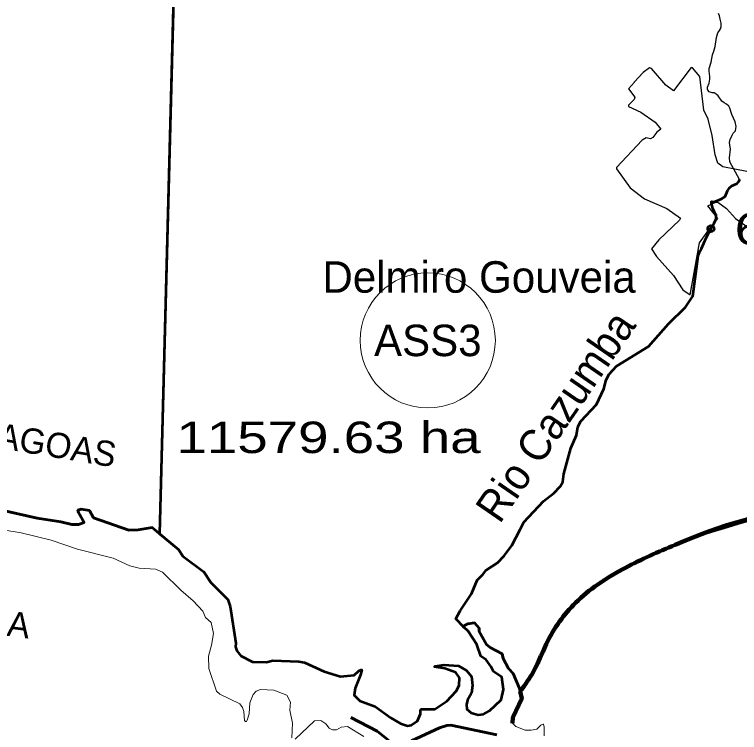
# Model space of a CAD drawing. Extents: x -1643653 to 4543381, y 1624270 to 13878484.
# Drawn here: x 598915 to 610437, y 8953418 to 8964825 of the extents above; entities that cross this region are included whole.
import ezdxf
from ezdxf.enums import TextEntityAlignment as Align

# ---------------------------------------------------------------- set-up
doc = ezdxf.new("R2010")
doc.units = 0
doc.header["$LTSCALE"] = 200
doc.header["$PDMODE"] = 32
doc.header["$PDSIZE"] = 100
doc.linetypes.add('LONG_DASH_SHORT_DASH', pattern=[9.9, 6, -1.2, 1.5, -1.2])
for name, color, linetype, lineweight in [('1', 7, 'Continuous', 13), ('21', 7, 'Continuous', 25), ('24', 7, 'Continuous', 25), ('25', 7, 'Continuous', 13), ('26', 7, 'Continuous', 106), ('27', 7, 'Continuous', 53), ('28', 7, 'Continuous', 53), ('45', 7, 'Continuous', 13), ('7', 7, 'LONG_DASH_SHORT_DASH', 60)]:
    doc.layers.add(name, color=color, linetype=linetype, lineweight=lineweight)
for name, color, linetype in [('41', 7, 'Continuous'), ('42', 7, 'Continuous'), ('49', 7, 'Continuous'), ('63', 7, 'Continuous')]:
    doc.layers.add(name, color=color, linetype=linetype)

msp = doc.modelspace()

# ---------------------------------------------------------------- linework, layer by layer
at = {"layer": '1', "lineweight": 25}
msp.add_spline([(814781, 9009175.5), (814787.2, 9009173.4), (814796.9, 9009173.4), (814799.4, 9009172.4), (814805.1, 9009174.5), (814805.6, 9009176.5), (814811.7, 9009179.5), (814811.7, 9009179.5), (814801.5, 9009181), (814790.7, 9009181.5), (814784.1, 9009183.1), (814777.4, 9009185.1), (814778.4, 9009175.5)], degree=3, dxfattribs=at)
at = {"layer": '21'}
for points in [[(609804.3, 8963841.6), (609692.8, 8963976.2), (609666.6, 8963982.7), (609387.8, 8963613.5), (609268.7, 8963704.3), (609037.7, 8963969.7), (609005.2, 8963976.3), (608907.9, 8963902.9), (608765.2, 8963749.4), (608768.4, 8963752.9)], [(608768.4, 8963752.9), (608671.8, 8963644.5), (608771.6, 8963513.5), (608763, 8963472.8), (608674.7, 8963384.3), (608674.6, 8963362.6), (608871.1, 8963271.6), (609098.6, 8963116.9), (609185.2, 8963006.2), (609122.6, 8962955.4), (609059.5, 8962870.7), (609020.3, 8962848.1), (608953.3, 8962867.3), (608890.2, 8962830.9), (608482.3, 8962396.3), (608482.2, 8962374.6), (608698.7, 8962069.7), (608927.4, 8961894.7), (609281.9, 8961745.5), (609500, 8961592.1), (609485, 8961557.5), (609154.4, 8961246.1), (609040.8, 8961101.4), (609119, 8960979.5), (609387.8, 8960677.5), (609534.3, 8960449.1), (609653.8, 8960372.8), (609800.8, 8961196.1)], [(610640.9, 8962315.2), (610391, 8962365.2), (610171.2, 8962405.2), (610091.2, 8962465.2), (610051.2, 8962595.2), (610001.3, 8962905.1), (609941.3, 8963165), (609871.4, 8963304.9), (609804.3, 8963841.6)], [(609800.8, 8961196.1), (609951.3, 8961405.5), (610091.2, 8961585.5), (609931.3, 8961785.4), (610001.3, 8961815.4), (610061.2, 8961845.4), (610091.2, 8961845.4), (610231.1, 8961745.4), (610371.1, 8961585.5), (610570.9, 8961445.5)]]:
    msp.add_lwpolyline(points, dxfattribs=at)
at = {"layer": '24'}
for points in [[(610371.4, 8962976.2), (610379.8, 8963013.8), (610382.1, 8963047.9), (610367.5, 8963120), (610314.8, 8963239.1), (610282.3, 8963338.2), (610265.4, 8963370.2), (610232.8, 8963402.2), (610193.3, 8963421.2), (610157.8, 8963448.2), (610095.6, 8963532.2), (610066.7, 8963561.2), (610036.6, 8963580.2), (610003.6, 8963581.1), (609956.2, 8963599.1), (609936, 8963623.1), (609928.6, 8963640.1), (609929.5, 8963669.1), (609954.4, 8963735.3), (609968.3, 8963800.4), (609967.7, 8963842.5), (609955.3, 8963923.6), (609957.6, 8963969.7), (609987.3, 8964065.8), (610009.7, 8964184.1), (610029.9, 8964242.2), (610049.4, 8964318.3), (610070.6, 8964459.6), (610090.6, 8964534.7), (610118.8, 8964569.8), (610136.5, 8964599.9), (610143.2, 8964627), (610143.3, 8964686.1), (610132.5, 8964751.1), (610117.5, 8964805.2), (610101.9, 8964839.2)], [(609982.1, 8961422.7), (610037.1, 8961507.9), (610064.5, 8961578.1), (610064.2, 8961638.2), (610040.6, 8961677.2), (610038.1, 8961690.2), (610013.3, 8961743.3), (609992.6, 8961823.3), (609993.5, 8961853.4), (609997.6, 8961856.4), (610025.7, 8961851.5), (610048.1, 8961855.5), (610148.5, 8961896.7), (610207.6, 8961933.9), (610245.1, 8962026.1), (610277.6, 8962073.2), (610312.8, 8962103.3), (610398.6, 8962138.5), (610419.5, 8962164.6), (610435.7, 8962195.6), (610437.2, 8962206.7), (610284.5, 8962485.8), (610279.8, 8962547.9), (610295.5, 8962684.2), (610281.3, 8962752.3), (610279.8, 8962791.3), (610289, 8962838.4), (610320, 8962910.6), (610338.8, 8962938.6), (610371.4, 8962976.2)], [(606950.7, 8956641.4), (607010.7, 8956757.8), (607320.7, 8957095.6), (607486.4, 8957220.9), (607586.3, 8957325.3), (607630.8, 8957401.7), (607645.7, 8957526.8), (607756.7, 8957933.8), (607847.4, 8958140.8), (607868.9, 8958272.7), (607915.5, 8958363.8), (608166.1, 8958629.3), (608279.8, 8958879.3), (608317, 8959022.3), (608365.8, 8959111.5), (608484.8, 8959236.8), (608990.2, 8959553.2), (609306.9, 8959910.2), (609576.6, 8960175.8), (609697.7, 8960350), (609780.5, 8960992), (609809.8, 8961070.9), (609834, 8961110), (609904.8, 8961278.4), (609982.1, 8961422.7)], [(606039.3, 8955103.8), (605929.6, 8955224.5), (605999.4, 8955353.7), (606180, 8955619.3), (606269.2, 8955840.2), (606360.2, 8955926.9), (606411.5, 8955999.5), (606589.9, 8956112.1), (606699.8, 8956226.1), (606821.6, 8956390.6), (606950.7, 8956641.4)]]:
    msp.add_lwpolyline(points, dxfattribs=at)
msp.add_point((609982.1, 8961422.7), dxfattribs=at)
at = {"layer": '25'}
for points in [[(604895.8, 8953649.4), (604648, 8953830.8), (604402.7, 8953921.2), (604313.5, 8954010.1), (604331.8, 8954124.8), (604416, 8954332.4), (604432.7, 8954411.5), (604424.9, 8954413.6), (604386.7, 8954398.7), (604315.2, 8954330), (604098.3, 8954307.6), (603837.5, 8954388.2), (603522.6, 8954529.5), (603434.3, 8954545.5), (603019.3, 8954562.1), (602920.8, 8954535.9), (602695.5, 8954541), (602512.3, 8954636.9), (602447.2, 8954715.8), (602427.7, 8954781.3), (602434.1, 8954838.6), (602343.7, 8955420.5), (602307.6, 8955528.7), (602034.6, 8955801.4), (601924, 8955971.4), (601588.5, 8956218.1), (601523.3, 8956327.4), (601101.6, 8956673.9), (600881.9, 8956635.9), (600732.9, 8956633.6), (600171.5, 8956830.7), (600105.7, 8956947.1), (599975.9, 8956965.8), (599923.2, 8956948.3), (599930.5, 8956912), (600022.6, 8956753.4), (599933.1, 8956722.5), (599825.2, 8956722.6), (599652.7, 8956767.8), (599276.6, 8956821.3), (598658.4, 8956963)], [(598729.6, 8956640.7), (599018.9, 8956591.1), (599495.2, 8956473.1), (599918.7, 8956332), (600484.8, 8956190.4), (600746.5, 8956064.1), (600895.5, 8956031), (601154.5, 8956013.6), (601268.1, 8955965.7), (601556.7, 8955677.2), (601755.9, 8955508), (601906.3, 8955346.6), (601953.1, 8955243.3), (602040.9, 8955167.5), (602075.2, 8954992.2), (602048.3, 8954806.2), (601997.4, 8954631), (602004.3, 8954436.4), (602125.1, 8954076), (602178.8, 8954026.5), (602495.4, 8953875), (602540.8, 8953812.8), (602559.9, 8953751), (602571, 8953609), (602585, 8953593.4), (602602.1, 8953591.9), (602614.5, 8953612.1), (602644, 8953712.8), (602654.8, 8953889.2), (602707.2, 8954022.7), (602755.2, 8954075.4), (602826.2, 8954100.6), (603037.5, 8954088.3), (603242.6, 8954010), (603302.4, 8953902.3), (603291.6, 8953774.8), (603334.3, 8953568.7), (603320.8, 8953334.8)], [(607330.5, 8953367), (607335.3, 8953510.5), (607319.8, 8953546.9), (607315.4, 8953548.9), (607278.7, 8953534.6), (607216.5, 8953473.1), (607127, 8953454.3), (607030.5, 8953457.3), (606882.1, 8953514.2), (606832.1, 8953564.1), (606835, 8953655.9), (606976.1, 8953957.7), (606939.6, 8954118.5), (606839.8, 8954356.2), (606764, 8954436.8), (606681.6, 8954591.6), (606663.8, 8954666.8), (606474.6, 8954769), (606419, 8954817.7), (606301.8, 8955025.5), (606297.6, 8955076.7), (606224.7, 8955160), (606120.8, 8955143.2), (606065.2, 8955120.1), (606045.1, 8955091.1), (606126.8, 8955027.9), (606264.5, 8954818.1), (606327.6, 8954629.3), (606412.6, 8954571)], [(606412.6, 8954571), (606492.4, 8954462.3), (606527.5, 8954387.4), (606659.3, 8954296.9), (606686, 8954102.5), (606651.8, 8953936.7), (606463.9, 8953759.9), (606370.3, 8953707.3), (606285.1, 8953700.2), (606172.6, 8953730.1), (606105.6, 8953789.7), (606098, 8953860.6), (606114.5, 8953932), (606175.8, 8954045.5), (606193.7, 8954164.2), (606175.7, 8954305.4), (606098.8, 8954404.1), (605973.2, 8954477.1), (605744.8, 8954495.8), (605598.2, 8954469.8), (605590.6, 8954462.3), (605753.2, 8954432.8), (605930.1, 8954372.2), (605986.4, 8954284.2), (605983.7, 8954165.7), (605933.2, 8954074.1), (605787.4, 8953917.3), (605593.6, 8953791), (605376.4, 8953790.1), (605366.2, 8953765.9), (605368.2, 8953714.1), (605319.2, 8953604.5), (605221.1, 8953536.7), (605160.9, 8953526.6), (605051.4, 8953560.8), (604895.8, 8953649.4)], [(603376.7, 8953311.5), (603681.8, 8953605.2), (603783.3, 8953607.1), (603860.4, 8953553.3), (603916.9, 8953484.5), (603968.4, 8953462.4), (604033.7, 8953462.8), (604105.8, 8953505.2), (604208, 8953515.8), (604469.3, 8953354.2)]]:
    msp.add_lwpolyline(points, dxfattribs=at)
at = {"layer": '26'}
msp.add_lwpolyline([(606950.6, 8954069.9), (606976.1, 8953957.7), (606835, 8953655.9), (606832.1, 8953564.1)], dxfattribs=at)
msp.add_spline([(645710.9, 8949471.4), (644721.9, 8950215.5), (643631.5, 8951123.7), (642665.6, 8952010.9), (642072.6, 8952588.9), (640582.3, 8953977.6), (638005.5, 8955508.7), (636255.8, 8956201.4), (634307.9, 8956672.6), (632583.3, 8956799.8), (628516.3, 8956628.1), (626161.4, 8955993.9), (623953.8, 8955209.7), (622371.6, 8954682.1), (620725.9, 8954192.9), (619183.7, 8953970.3), (617209.7, 8953965.7), (615658.4, 8954379), (614681.6, 8955057.1), (613704.6, 8955684.2), (612906.2, 8956374.2), (612068.3, 8956835.4), (609416.9, 8956401.3), (608625.2, 8956035.7), (607870.9, 8955517.4), (607396.1, 8954883.6), (607164, 8954388.6), (606950.6, 8954069.9)], degree=3, dxfattribs=at)
at = {"layer": '27'}
msp.add_line((601511.4, 8967709.9), (601221.6, 8956575.3), dxfattribs=at)
for points in [[(601400, 8967810.3), (601511.4, 8967709.9), (601221.6, 8956575.3)], [(609982.1, 8961422.7), (610037.1, 8961507.9), (610064.5, 8961578.1), (610064.2, 8961638.2), (610040.6, 8961677.2), (610038.1, 8961690.2), (610013.3, 8961743.3), (609992.6, 8961823.3), (609993.5, 8961853.4), (609997.6, 8961856.4), (610025.7, 8961851.5), (610048.1, 8961855.5), (610148.5, 8961896.7), (610207.6, 8961933.9), (610245.1, 8962026.1), (610277.6, 8962073.2), (610312.8, 8962103.3), (610398.6, 8962138.5), (610419.5, 8962164.6), (610435.7, 8962195.6), (610437.2, 8962206.7)], [(610277.6, 8962073.2), (610312.8, 8962103.3), (610398.6, 8962138.5), (610419.5, 8962164.6), (610435.7, 8962195.6), (610437.2, 8962206.7)], [(606950.7, 8956641.4), (607010.7, 8956757.8), (607320.7, 8957095.6), (607486.4, 8957220.9), (607586.3, 8957325.3), (607630.8, 8957401.7), (607645.7, 8957526.8), (607756.7, 8957933.8), (607847.4, 8958140.8), (607868.9, 8958272.7), (607915.5, 8958363.8), (608166.1, 8958629.3), (608279.8, 8958879.3), (608317, 8959022.3), (608365.8, 8959111.5), (608484.8, 8959236.8), (608990.2, 8959553.2), (609306.9, 8959910.2), (609576.6, 8960175.8), (609697.7, 8960350), (609780.5, 8960992), (609809.8, 8961070.9), (609834, 8961110), (609904.8, 8961278.4), (609982.1, 8961422.7), (610037.1, 8961507.9), (610064.5, 8961578.1), (610064.2, 8961638.2), (610040.6, 8961677.2), (610038.1, 8961690.2), (610013.3, 8961743.3), (609992.6, 8961823.3), (609993.5, 8961853.4), (609997.6, 8961856.4), (610025.7, 8961851.5), (610048.1, 8961855.5), (610148.5, 8961896.7), (610207.6, 8961933.9), (610245.1, 8962026.1), (610277.6, 8962073.2)], [(606950.7, 8956641.4), (607010.7, 8956757.8), (607320.7, 8957095.6), (607486.4, 8957220.9), (607586.3, 8957325.3), (607630.8, 8957401.7), (607645.7, 8957526.8), (607756.7, 8957933.8), (607847.4, 8958140.8), (607868.9, 8958272.7), (607915.5, 8958363.8), (608166.1, 8958629.3), (608279.8, 8958879.3), (608317, 8959022.3), (608365.8, 8959111.5), (608484.8, 8959236.8), (608990.2, 8959553.2), (609306.9, 8959910.2), (609576.6, 8960175.8), (609697.7, 8960350), (609780.5, 8960992), (609809.8, 8961070.9), (609834, 8961110), (609904.8, 8961278.4), (609982.1, 8961422.7)], [(601221.6, 8956575.3), (601101.6, 8956673.9), (600881.9, 8956635.9), (600732.9, 8956633.6), (600171.5, 8956830.7), (600105.7, 8956947.1), (599975.9, 8956965.8), (599923.2, 8956948.3), (599930.5, 8956912), (600022.6, 8956753.4), (599933.1, 8956722.5), (599825.2, 8956722.6), (599652.7, 8956767.8), (599276.6, 8956821.3), (598658.4, 8956963)], [(606049.2, 8955097), (605929.6, 8955224.5), (605999.4, 8955353.7), (606180, 8955619.3), (606269.2, 8955840.2), (606360.2, 8955926.9), (606411.5, 8955999.5), (606589.9, 8956112.1), (606699.8, 8956226.1), (606821.6, 8956390.6), (606950.7, 8956641.4)], [(606049.2, 8955097), (605929.6, 8955224.5), (605999.4, 8955353.7), (606180, 8955619.3), (606269.2, 8955840.2), (606360.2, 8955926.9), (606411.5, 8955999.5), (606589.9, 8956112.1), (606699.8, 8956226.1), (606821.6, 8956390.6), (606950.7, 8956641.4)], [(601221.6, 8956575.3), (601523.3, 8956327.4), (601588.5, 8956218.1), (601924, 8955971.4), (602034.6, 8955801.4), (602307.6, 8955528.7), (602343.7, 8955420.5), (602434.1, 8954838.6), (602427.7, 8954781.3), (602447.2, 8954715.8), (602512.3, 8954636.9), (602695.5, 8954541), (602920.8, 8954535.9), (603019.3, 8954562.1), (603434.3, 8954545.5), (603522.6, 8954529.5), (603837.5, 8954388.2), (604098.3, 8954307.6), (604315.2, 8954330), (604386.7, 8954398.7), (604424.9, 8954413.6), (604432.7, 8954411.5), (604416, 8954332.4), (604331.8, 8954124.8), (604313.5, 8954010.1), (604402.7, 8953921.2), (604648, 8953830.8), (604895.8, 8953649.4)], [(606949.2, 8954076.2), (606939.6, 8954118.5), (606839.8, 8954356.2), (606764, 8954436.8), (606681.6, 8954591.6), (606663.8, 8954666.8), (606474.6, 8954769), (606419, 8954817.7), (606301.8, 8955025.5), (606297.6, 8955076.7), (606224.7, 8955160), (606120.8, 8955143.2), (606065.2, 8955120.1), (606049.2, 8955097)], [(606412.6, 8954571), (606327.6, 8954629.3), (606264.5, 8954818.1), (606126.8, 8955027.9), (606049.2, 8955097)], [(604895.8, 8953649.4), (605051.4, 8953560.8), (605160.9, 8953526.6), (605221.1, 8953536.7), (605319.2, 8953604.5), (605368.2, 8953714.1), (605366.2, 8953765.9), (605376.4, 8953790.1), (605593.6, 8953791), (605787.4, 8953917.3), (605933.2, 8954074.1), (605983.7, 8954165.7), (605986.4, 8954284.2), (605930.1, 8954372.2), (605753.2, 8954432.8), (605590.6, 8954462.3), (605598.2, 8954469.8), (605744.8, 8954495.8), (605973.2, 8954477.1), (606098.8, 8954404.1), (606175.7, 8954305.4), (606193.7, 8954164.2), (606175.8, 8954045.5), (606114.5, 8953932), (606098, 8953860.6), (606105.6, 8953789.7), (606172.6, 8953730.1), (606285.1, 8953700.2), (606370.3, 8953707.3), (606463.9, 8953759.9), (606651.8, 8953936.7), (606686, 8954102.5), (606659.3, 8954296.9), (606527.5, 8954387.4), (606492.4, 8954462.3), (606412.6, 8954571)]]:
    msp.add_lwpolyline(points, dxfattribs=at)
for points in [[(612430.2, 8956693.8), (612068.3, 8956835.4), (609908.8, 8956579.1)], [(609908.8, 8956579.1), (609416.9, 8956401.3), (608625.2, 8956035.7), (607870.9, 8955517.4), (607396.1, 8954883.6), (607164, 8954388.6), (606956.6, 8954077.8)]]:
    msp.add_spline(points, degree=3, dxfattribs=at)
msp.add_point((609982.1, 8961422.7), dxfattribs=at)
at = {"layer": '28'}
for points in [[(598658.4, 8956963), (599276.6, 8956821.3), (599652.7, 8956767.8), (599825.2, 8956722.6), (599933.1, 8956722.5), (600022.6, 8956753.4), (599930.5, 8956912), (599923.2, 8956948.3), (599975.9, 8956965.8), (600105.7, 8956947.1), (600171.5, 8956830.7), (600732.9, 8956633.6), (600881.9, 8956635.9), (601101.6, 8956673.9), (601523.3, 8956327.4), (601588.5, 8956218.1), (601924, 8955971.4), (602034.6, 8955801.4), (602307.6, 8955528.7), (602343.7, 8955420.5), (602434.1, 8954838.6), (602427.7, 8954781.3), (602447.2, 8954715.8), (602512.3, 8954636.9), (602695.5, 8954541), (602920.8, 8954535.9), (603019.3, 8954562.1), (603434.3, 8954545.5), (603522.6, 8954529.5), (603837.5, 8954388.2), (604098.3, 8954307.6), (604315.2, 8954330), (604386.7, 8954398.7), (604424.9, 8954413.6), (604432.7, 8954411.5), (604416, 8954332.4), (604331.8, 8954124.8), (604313.5, 8954010.1), (604402.7, 8953921.2), (604648, 8953830.8), (604895.8, 8953649.4)], [(598658.4, 8956963), (599276.6, 8956821.3), (599652.7, 8956767.8), (599825.2, 8956722.6), (599933.1, 8956722.5), (600022.6, 8956753.4), (599930.5, 8956912), (599923.2, 8956948.3), (599975.9, 8956965.8), (600105.7, 8956947.1), (600171.5, 8956830.7), (600732.9, 8956633.6), (600881.9, 8956635.9), (601101.6, 8956673.9), (601523.3, 8956327.4), (601588.5, 8956218.1), (601924, 8955971.4), (602034.6, 8955801.4), (602307.6, 8955528.7), (602343.7, 8955420.5), (602434.1, 8954838.6), (602427.7, 8954781.3), (602447.2, 8954715.8), (602512.3, 8954636.9), (602695.5, 8954541), (602920.8, 8954535.9), (603019.3, 8954562.1), (603434.3, 8954545.5), (603522.6, 8954529.5), (603837.5, 8954388.2), (604098.3, 8954307.6), (604315.2, 8954330), (604386.7, 8954398.7), (604424.9, 8954413.6), (604432.7, 8954411.5), (604416, 8954332.4), (604331.8, 8954124.8), (604313.5, 8954010.1), (604402.7, 8953921.2), (604648, 8953830.8), (604895.8, 8953649.4)], [(606412.6, 8954571), (606327.6, 8954629.3), (606264.5, 8954818.1), (606126.8, 8955027.9), (606045.1, 8955091.1), (606065.2, 8955120.1), (606120.8, 8955143.2), (606224.7, 8955160), (606297.6, 8955076.7), (606301.8, 8955025.5), (606419, 8954817.7), (606474.6, 8954769), (606663.8, 8954666.8), (606681.6, 8954591.6), (606764, 8954436.8), (606839.8, 8954356.2), (606939.6, 8954118.5), (606949.2, 8954076.2), (606956.6, 8954077.8)], [(606412.6, 8954571), (606327.6, 8954629.3), (606264.5, 8954818.1), (606126.8, 8955027.9), (606045.1, 8955091.1), (606065.2, 8955120.1), (606120.8, 8955143.2), (606224.7, 8955160), (606297.6, 8955076.7), (606301.8, 8955025.5), (606419, 8954817.7), (606474.6, 8954769), (606663.8, 8954666.8), (606681.6, 8954591.6), (606764, 8954436.8), (606839.8, 8954356.2), (606939.6, 8954118.5), (606949.2, 8954076.2), (606956.6, 8954077.8)], [(604895.8, 8953649.4), (605051.4, 8953560.8), (605160.9, 8953526.6), (605221.1, 8953536.7), (605319.2, 8953604.5), (605368.2, 8953714.1), (605366.2, 8953765.9), (605376.4, 8953790.1), (605593.6, 8953791), (605787.4, 8953917.3), (605933.2, 8954074.1), (605983.7, 8954165.7), (605986.4, 8954284.2), (605930.1, 8954372.2), (605753.2, 8954432.8), (605590.6, 8954462.3), (605598.2, 8954469.8), (605744.8, 8954495.8), (605973.2, 8954477.1), (606098.8, 8954404.1), (606175.7, 8954305.4), (606193.7, 8954164.2), (606175.8, 8954045.5), (606114.5, 8953932), (606098, 8953860.6), (606105.6, 8953789.7), (606172.6, 8953730.1), (606285.1, 8953700.2), (606370.3, 8953707.3), (606463.9, 8953759.9), (606651.8, 8953936.7), (606686, 8954102.5), (606659.3, 8954296.9), (606527.5, 8954387.4), (606492.4, 8954462.3), (606412.6, 8954571)], [(604895.8, 8953649.4), (605051.4, 8953560.8), (605160.9, 8953526.6), (605221.1, 8953536.7), (605319.2, 8953604.5), (605368.2, 8953714.1), (605366.2, 8953765.9), (605376.4, 8953790.1), (605593.6, 8953791), (605787.4, 8953917.3), (605933.2, 8954074.1), (605983.7, 8954165.7), (605986.4, 8954284.2), (605930.1, 8954372.2), (605753.2, 8954432.8), (605590.6, 8954462.3), (605598.2, 8954469.8), (605744.8, 8954495.8), (605973.2, 8954477.1), (606098.8, 8954404.1), (606175.7, 8954305.4), (606193.7, 8954164.2), (606175.8, 8954045.5), (606114.5, 8953932), (606098, 8953860.6), (606105.6, 8953789.7), (606172.6, 8953730.1), (606285.1, 8953700.2), (606370.3, 8953707.3), (606463.9, 8953759.9), (606651.8, 8953936.7), (606686, 8954102.5), (606659.3, 8954296.9), (606527.5, 8954387.4), (606492.4, 8954462.3), (606412.6, 8954571)]]:
    msp.add_lwpolyline(points, dxfattribs=at)
msp.add_spline([(606956.6, 8954077.8), (607164, 8954388.6), (607396.1, 8954883.6), (607870.9, 8955517.4), (608625.2, 8956035.7), (609416.9, 8956401.3), (612068.3, 8956835.4), (612430.2, 8956693.8)], degree=3, dxfattribs=at)
msp.add_spline([(606956.6, 8954077.8), (607164, 8954388.6), (607396.1, 8954883.6), (607870.9, 8955517.4), (608625.2, 8956035.7), (609416.9, 8956401.3), (612068.3, 8956835.4), (612430.2, 8956693.8)], degree=3, dxfattribs=at)
at = {"layer": '45'}
msp.add_circle((605483.4, 8959647.6), 1073.6, dxfattribs=at)
at = {"layer": '7'}
for points in [[(604260.6, 8953658.9), (604677.1, 8953437.9), (604865.4, 8953293)], [(605226.7, 8953286.6), (605667.4, 8953494), (605788.2, 8953530.6), (605849.3, 8953532.9), (606579.7, 8953379.4)]]:
    msp.add_lwpolyline(points, dxfattribs=at)

# ---------------------------------------------------------------- texts
at = {"layer": '41'}
msp.add_text('Delmiro Gouveia', height=500, dxfattribs=at).set_placement((603808.9, 8960405.2))
at = {"layer": '42'}
for s, rotation, p in [('ALAGOAS', 350.452, (599232.2, 8957841.5)), ('BAHIA', 352.646, (598339.8, 8955012.7))]:
    msp.add_text(s, height=400, rotation=rotation, dxfattribs=at).set_placement(p, align=Align.CENTER)
at = {"layer": '45'}
msp.add_text('ASS3', height=500, dxfattribs=at).set_placement((605483.5, 8959397.6), align=Align.CENTER)
at = {"layer": '49', "width": 0.95}
msp.add_text('Rio Cazumba', height=500, rotation=55.429, dxfattribs=at).set_placement((607716.8, 8958303), align=Align.CENTER)
at = {"layer": '63', "width": 1.3}
for s, p in [(' 6113.23 ha', (610118.3, 8961168.6)), (' 11579.63 ha', (601247.2, 8957857.7))]:
    msp.add_text(s, height=500, dxfattribs=at).set_placement(p)

doc.saveas('drawing.dxf')
